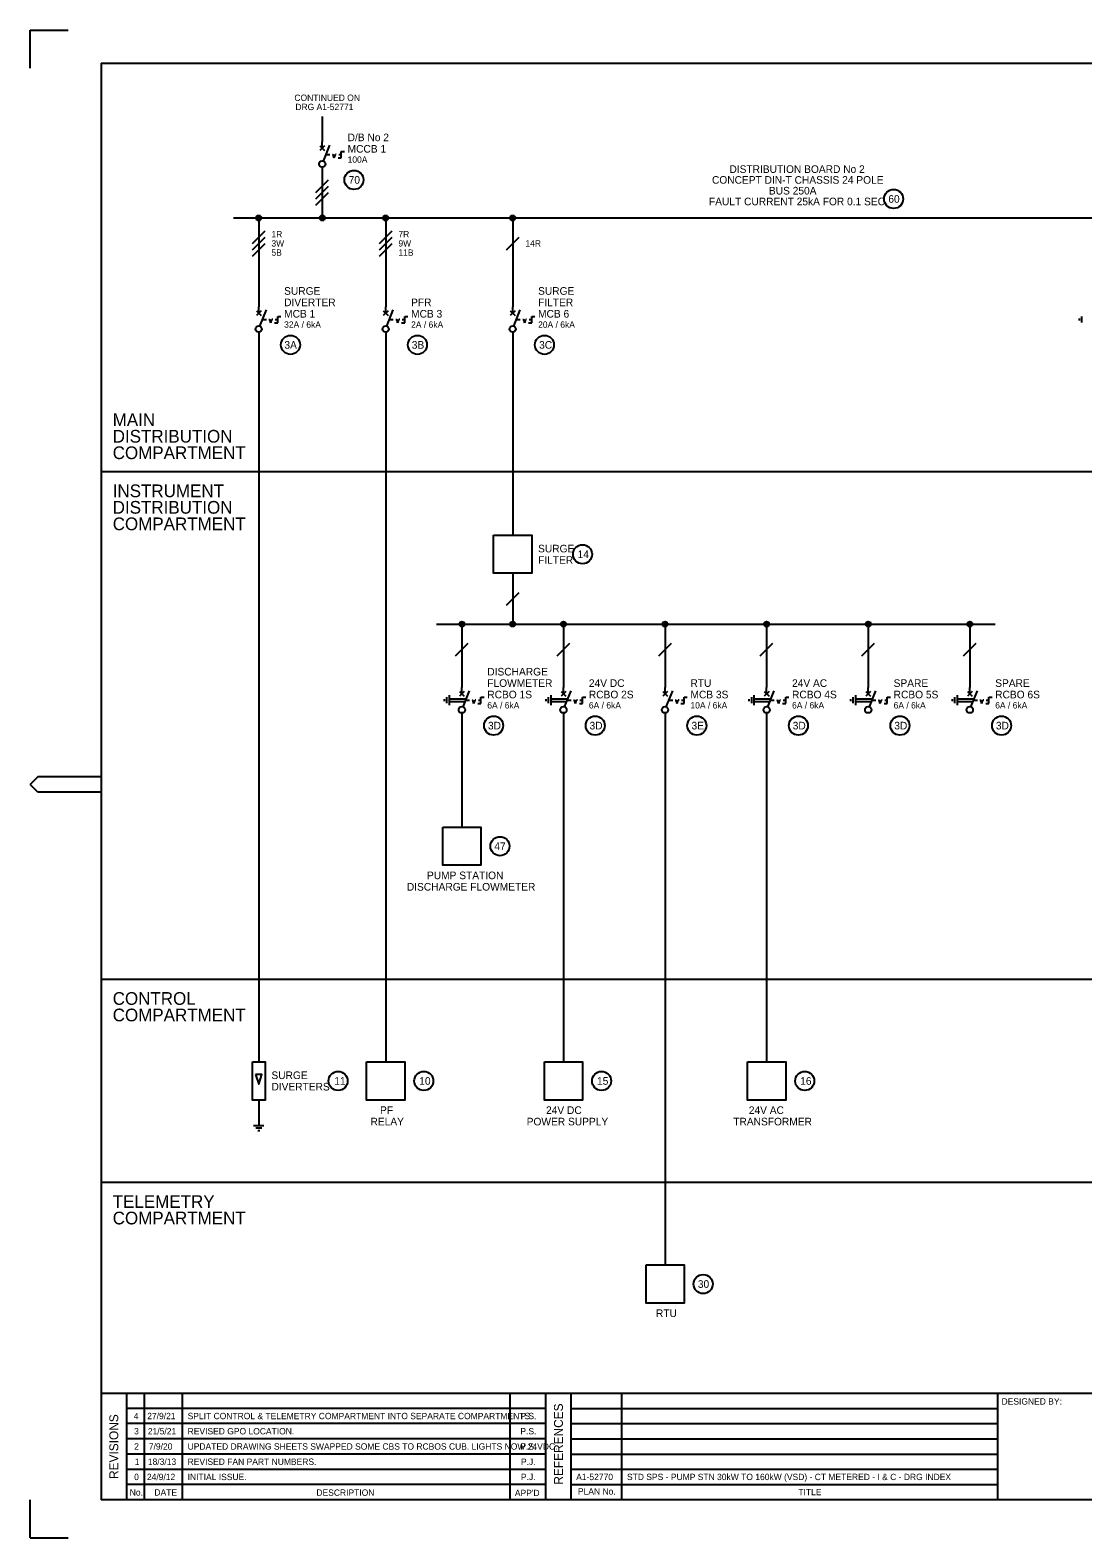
# Model space of a CAD drawing. Extents: x 0 to 841, y 0 to 594.
# Drawn here: x 0 to 414, y 0 to 594 of the extents above; entities that cross this region are included whole.
import ezdxf

# ---------------------------------------------------------------- set-up
doc = ezdxf.new("R2010")
doc.units = 0
for name, color, linetype in [('A1BORDER', 7, 'Continuous'), ('Level 1', 7, 'Continuous'), ('Level 10', 7, 'Continuous')]:
    doc.layers.add(name, color=color, linetype=linetype)

msp = doc.modelspace()

# ---------------------------------------------------------------- linework, layer by layer
at = {"layer": 'A1BORDER'}
for p, q in [((0, 594), (15, 594)), ((0, 579), (0, 594)), ((28, 581), (829, 581)), ((28, 581), (28, 15)), ((3, 299.76), (0, 296.76)), ((28, 299.76), (3, 299.76)), ((3, 293.76), (0, 296.76)), ((28, 293.76), (3, 293.76)), ((28, 57), (829, 57)), ((38, 15), (38, 57)), ((45, 15), (45, 57)), ((60, 15), (60, 57)), ((189, 15), (189, 57)), ((203, 15), (203, 57)), ((213, 15), (213, 57)), ((233, 15), (233, 57)), ((381, 15), (381, 57)), ((203, 51), (38, 51)), ((213, 51), (381, 51)), ((203, 45), (38, 45)), ((213, 45), (381, 45)), ((203, 39), (38, 39)), ((213, 39), (381, 39)), ((203, 33), (38, 33)), ((213, 33), (381, 33)), ((38, 27), (203, 27)), ((213, 27), (381, 27)), ((203, 21), (38, 21)), ((213, 21), (381, 21)), ((0, 0), (0, 15)), ((829, 15), (28, 15)), ((0, 0), (15, 0))]:
    msp.add_line(p, q, dxfattribs=at)
at = {"layer": 'Level 1'}
for p, q in [((115, 560), (115, 550)), ((114.06, 548.44), (115.94, 546.56)), ((115.94, 548.44), (114.06, 546.56)), ((115, 547.5), (115, 550)), ((115.46, 542.41), (118, 548.75)), ((112.5, 530), (117.5, 535)), ((115, 540), (115, 520)), ((112.5, 527.5), (117.5, 532.5)), ((112.5, 525), (117.5, 530)), ((80, 520), (740, 520)), ((90, 520), (90, 485)), ((140, 520), (140, 485)), ((190, 520), (190, 485)), ((87.5, 510), (92.5, 515)), ((87.5, 507.5), (92.5, 512.5)), ((137.5, 510), (142.5, 515)), ((137.5, 507.5), (142.5, 512.5)), ((187.5, 507.5), (192.5, 512.5)), ((87.5, 505), (92.5, 510)), ((137.5, 505), (142.5, 510)), ((89.06, 483.44), (90.94, 481.56)), ((90.94, 483.44), (89.06, 481.56)), ((90, 482.5), (90, 485)), ((90.46, 477.41), (93, 483.75)), ((139.06, 483.44), (140.94, 481.56)), ((140.94, 483.44), (139.06, 481.56)), ((140, 482.5), (140, 485)), ((140.46, 477.41), (143, 483.75)), ((189.06, 483.44), (190.94, 481.56)), ((190.94, 483.44), (189.06, 481.56)), ((190, 482.5), (190, 485)), ((190.46, 477.41), (193, 483.75)), ((90, 475), (90, 187.5)), ((140, 475), (140, 187.5)), ((190, 475), (190, 395)), ((829, 420), (28, 420)), ((190, 380), (190, 360)), ((187.5, 367.5), (192.5, 372.5)), ((160, 360), (380, 360)), ((170, 360), (170, 335)), ((210, 360), (210, 335)), ((250, 360), (250, 335)), ((290, 360), (290, 335)), ((330, 360), (330, 335)), ((370, 360), (370, 335)), ((167.5, 347.5), (172.5, 352.5)), ((207.5, 347.5), (212.5, 352.5)), ((247.5, 347.5), (252.5, 352.5)), ((287.5, 347.5), (292.5, 352.5)), ((327.5, 347.5), (332.5, 352.5)), ((367.5, 347.5), (372.5, 352.5)), ((169.06, 333.44), (170.94, 331.56)), ((170.94, 333.44), (169.06, 331.56)), ((170, 332.5), (170, 335)), ((170.46, 327.41), (173, 333.75)), ((209.06, 333.44), (210.94, 331.56)), ((210.94, 333.44), (209.06, 331.56)), ((210, 332.5), (210, 335)), ((210.46, 327.41), (213, 333.75)), ((249.06, 333.44), (250.94, 331.56)), ((250.94, 333.44), (249.06, 331.56)), ((250, 332.5), (250, 335)), ((250.46, 327.41), (253, 333.75)), ((289.06, 333.44), (290.94, 331.56)), ((290.94, 333.44), (289.06, 331.56)), ((290, 332.5), (290, 335)), ((290.46, 327.41), (293, 333.75)), ((329.06, 333.44), (330.94, 331.56)), ((330.94, 333.44), (329.06, 331.56)), ((330, 332.5), (330, 335)), ((330.46, 327.41), (333, 333.75)), ((369.06, 333.44), (370.94, 331.56)), ((370.94, 333.44), (369.06, 331.56)), ((370, 332.5), (370, 335)), ((370.46, 327.41), (373, 333.75)), ((165, 330.5), (171.7, 330.5)), ((165, 329.5), (171.3, 329.5)), ((205, 330.5), (211.7, 330.5)), ((205, 329.5), (211.3, 329.5)), ((285, 330.5), (291.7, 330.5)), ((285, 329.5), (291.3, 329.5)), ((325, 330.5), (331.7, 330.5)), ((325, 329.5), (331.3, 329.5)), ((365, 330.5), (371.7, 330.5)), ((365, 329.5), (371.3, 329.5)), ((170, 325), (170, 280)), ((210, 325), (210, 187.5)), ((250, 325), (250, 107.5)), ((290, 325), (290, 187.5)), ((829, 220), (28, 220)), ((90, 172.5), (90, 162.5)), ((480, 140), (28, 140))]:
    msp.add_line(p, q, dxfattribs=at)
for points in [[(182.5, 395), (197.5, 395), (197.5, 380), (182.5, 380)], [(162.5, 280), (177.5, 280), (177.5, 265), (162.5, 265)], [(87.5, 187.5), (92.5, 187.5), (92.5, 172.5), (87.5, 172.5)], [(132.5, 187.5), (147.5, 187.5), (147.5, 172.5), (132.5, 172.5)], [(202.5, 187.5), (217.5, 187.5), (217.5, 172.5), (202.5, 172.5)], [(282.5, 187.5), (297.5, 187.5), (297.5, 172.5), (282.5, 172.5)], [(88.75, 182.5), (90, 178.75), (91.25, 182.5)], [(242.5, 107.5), (257.5, 107.5), (257.5, 92.5), (242.5, 92.5)]]:
    msp.add_lwpolyline(points, close=True, dxfattribs=at)
for centre, radius in [((115, 541.25), 1.25), ((127.5, 535), 3.75), ((340, 527.5), 3.75), ((90, 476.25), 1.25), ((140, 476.25), 1.25), ((190, 476.25), 1.25), ((102.5, 470), 3.75), ((152.5, 470), 3.75), ((202.5, 470), 3.75), ((217.5, 387.5), 3.75), ((170, 326.25), 1.25), ((210, 326.25), 1.25), ((250, 326.25), 1.25), ((290, 326.25), 1.25), ((330, 326.25), 1.25), ((370, 326.25), 1.25), ((182.5, 320), 3.75), ((222.5, 320), 3.75), ((262.5, 320), 3.75), ((302.5, 320), 3.75), ((342.5, 320), 3.75), ((382.5, 320), 3.75), ((185, 272.5), 3.75), ((121.25, 180), 3.75), ((155, 180), 3.75), ((225, 180), 3.75), ((305, 180), 3.75), ((265, 100), 3.75)]:
    msp.add_circle(centre, radius, dxfattribs=at)
at = {"layer": 'Level 10'}
for p, q in [((116.5, 545), (118, 545)), ((119, 545), (119.33, 545)), ((119.75, 543.75), (119.33, 545)), ((119.75, 543.75), (120.17, 545)), ((120.5, 545), (120.17, 545)), ((121.25, 543.75), (122.5, 543.75)), ((121.5, 545), (122.5, 545)), ((122.5, 543.75), (122.5, 546.25)), ((122.5, 546.25), (123.75, 546.25)), ((89.01, 520.1), (90.99, 520.1)), ((89.02, 519.8), (90.98, 519.8)), ((89.08, 520.4), (90.92, 520.4)), ((89.13, 519.5), (90.87, 519.5)), ((89.29, 520.7), (90.71, 520.7)), ((89.4, 519.2), (90.6, 519.2)), ((90, 521), (90, 521)), ((114.01, 520.1), (115.99, 520.1)), ((114.02, 519.8), (115.98, 519.8)), ((114.08, 520.4), (115.92, 520.4)), ((114.13, 519.5), (115.87, 519.5)), ((114.29, 520.7), (115.71, 520.7)), ((114.4, 519.2), (115.6, 519.2)), ((115, 521), (115, 521)), ((139.01, 520.1), (140.99, 520.1)), ((139.02, 519.8), (140.98, 519.8)), ((139.08, 520.4), (140.92, 520.4)), ((139.13, 519.5), (140.87, 519.5)), ((139.29, 520.7), (140.71, 520.7)), ((139.4, 519.2), (140.6, 519.2)), ((140, 521), (140, 521)), ((189.01, 520.1), (190.99, 520.1)), ((189.02, 519.8), (190.98, 519.8)), ((189.08, 520.4), (190.92, 520.4)), ((189.13, 519.5), (190.87, 519.5)), ((189.29, 520.7), (190.71, 520.7)), ((189.4, 519.2), (190.6, 519.2)), ((190, 521), (190, 521)), ((97.5, 478.75), (97.5, 481.25)), ((97.5, 481.25), (98.75, 481.25)), ((147.5, 478.75), (147.5, 481.25)), ((147.5, 481.25), (148.75, 481.25)), ((197.5, 478.75), (197.5, 481.25)), ((197.5, 481.25), (198.75, 481.25)), ((414, 481.2), (414, 478.8)), ((91.5, 480), (93, 480)), ((94, 480), (94.33, 480)), ((94.75, 478.75), (94.33, 480)), ((94.75, 478.75), (95.17, 480)), ((95.5, 480), (95.17, 480)), ((96.25, 478.75), (97.5, 478.75)), ((96.5, 480), (97.5, 480)), ((141.5, 480), (143, 480)), ((144, 480), (144.33, 480)), ((144.75, 478.75), (144.33, 480)), ((144.75, 478.75), (145.17, 480)), ((145.5, 480), (145.17, 480)), ((146.25, 478.75), (147.5, 478.75)), ((146.5, 480), (147.5, 480)), ((191.5, 480), (193, 480)), ((194, 480), (194.33, 480)), ((194.75, 478.75), (194.33, 480)), ((194.75, 478.75), (195.17, 480)), ((195.5, 480), (195.17, 480)), ((196.25, 478.75), (197.5, 478.75)), ((196.5, 480), (197.5, 480)), ((413, 480.4), (413, 479.6)), ((169.01, 360.1), (170.99, 360.1)), ((169.02, 359.8), (170.98, 359.8)), ((169.08, 360.4), (170.92, 360.4)), ((169.13, 359.5), (170.87, 359.5)), ((169.29, 360.7), (170.71, 360.7)), ((169.4, 359.2), (170.6, 359.2)), ((170, 361), (170, 361)), ((189.01, 360.1), (190.99, 360.1)), ((189.02, 359.8), (190.98, 359.8)), ((189.08, 360.4), (190.92, 360.4)), ((189.13, 359.5), (190.87, 359.5)), ((189.29, 360.7), (190.71, 360.7)), ((189.4, 359.2), (190.6, 359.2)), ((190, 361), (190, 361)), ((209.01, 360.1), (210.99, 360.1)), ((209.02, 359.8), (210.98, 359.8)), ((209.08, 360.4), (210.92, 360.4)), ((209.13, 359.5), (210.87, 359.5)), ((209.29, 360.7), (210.71, 360.7)), ((209.4, 359.2), (210.6, 359.2)), ((210, 361), (210, 361)), ((249.01, 360.1), (250.99, 360.1)), ((249.02, 359.8), (250.98, 359.8)), ((249.08, 360.4), (250.92, 360.4)), ((249.13, 359.5), (250.87, 359.5)), ((249.29, 360.7), (250.71, 360.7)), ((249.4, 359.2), (250.6, 359.2)), ((250, 361), (250, 361)), ((289.01, 360.1), (290.99, 360.1)), ((289.02, 359.8), (290.98, 359.8)), ((289.08, 360.4), (290.92, 360.4)), ((289.13, 359.5), (290.87, 359.5)), ((289.29, 360.7), (290.71, 360.7)), ((289.4, 359.2), (290.6, 359.2)), ((290, 361), (290, 361)), ((329.01, 360.1), (330.99, 360.1)), ((329.02, 359.8), (330.98, 359.8)), ((329.08, 360.4), (330.92, 360.4)), ((329.13, 359.5), (330.87, 359.5)), ((329.29, 360.7), (330.71, 360.7)), ((329.4, 359.2), (330.6, 359.2)), ((330, 361), (330, 361)), ((369.01, 360.1), (370.99, 360.1)), ((369.02, 359.8), (370.98, 359.8)), ((369.08, 360.4), (370.92, 360.4)), ((369.13, 359.5), (370.87, 359.5)), ((369.29, 360.7), (370.71, 360.7)), ((369.4, 359.2), (370.6, 359.2)), ((370, 361), (370, 361)), ((163, 330.4), (163, 329.6)), ((164, 331.2), (164, 328.8)), ((165, 332), (165, 328)), ((171.5, 330), (173, 330)), ((174, 330), (174.33, 330)), ((174.75, 328.75), (174.33, 330)), ((174.75, 328.75), (175.17, 330)), ((175.5, 330), (175.17, 330)), ((176.25, 328.75), (177.5, 328.75)), ((176.5, 330), (177.5, 330)), ((177.5, 328.75), (177.5, 331.25)), ((177.5, 331.25), (178.75, 331.25)), ((203, 330.4), (203, 329.6)), ((204, 331.2), (204, 328.8)), ((205, 332), (205, 328)), ((211.5, 330), (213, 330)), ((214, 330), (214.33, 330)), ((214.75, 328.75), (214.33, 330)), ((214.75, 328.75), (215.17, 330)), ((215.5, 330), (215.17, 330)), ((216.25, 328.75), (217.5, 328.75)), ((216.5, 330), (217.5, 330)), ((217.5, 328.75), (217.5, 331.25)), ((217.5, 331.25), (218.75, 331.25)), ((251.5, 330), (253, 330)), ((254, 330), (254.33, 330)), ((254.75, 328.75), (254.33, 330)), ((254.75, 328.75), (255.17, 330)), ((255.5, 330), (255.17, 330)), ((256.25, 328.75), (257.5, 328.75)), ((256.5, 330), (257.5, 330)), ((257.5, 328.75), (257.5, 331.25)), ((257.5, 331.25), (258.75, 331.25)), ((283, 330.4), (283, 329.6)), ((284, 331.2), (284, 328.8)), ((285, 332), (285, 328)), ((291.5, 330), (293, 330)), ((294, 330), (294.33, 330)), ((294.75, 328.75), (294.33, 330)), ((294.75, 328.75), (295.17, 330)), ((295.5, 330), (295.17, 330)), ((296.25, 328.75), (297.5, 328.75)), ((296.5, 330), (297.5, 330)), ((297.5, 328.75), (297.5, 331.25)), ((297.5, 331.25), (298.75, 331.25)), ((323, 330.4), (323, 329.6)), ((324, 331.2), (324, 328.8)), ((325, 332), (325, 328)), ((331.5, 330), (333, 330)), ((334, 330), (334.33, 330)), ((334.75, 328.75), (334.33, 330)), ((334.75, 328.75), (335.17, 330)), ((335.5, 330), (335.17, 330)), ((336.25, 328.75), (337.5, 328.75)), ((336.5, 330), (337.5, 330)), ((337.5, 328.75), (337.5, 331.25)), ((337.5, 331.25), (338.75, 331.25)), ((363, 330.4), (363, 329.6)), ((364, 331.2), (364, 328.8)), ((365, 332), (365, 328)), ((371.5, 330), (373, 330)), ((374, 330), (374.33, 330)), ((374.75, 328.75), (374.33, 330)), ((374.75, 328.75), (375.17, 330)), ((375.5, 330), (375.17, 330)), ((376.25, 328.75), (377.5, 328.75)), ((376.5, 330), (377.5, 330)), ((377.5, 328.75), (377.5, 331.25)), ((377.5, 331.25), (378.75, 331.25)), ((88, 162.5), (92, 162.5)), ((88.8, 161.5), (91.2, 161.5)), ((89.6, 160.5), (90.4, 160.5))]:
    msp.add_line(p, q, dxfattribs=at)
for centre in [(90, 520), (115, 520), (140, 520), (190, 520), (170, 360), (190, 360), (210, 360), (250, 360), (290, 360), (330, 360), (370, 360)]:
    msp.add_circle(centre, 1, dxfattribs=at)

# ---------------------------------------------------------------- texts
at = {"layer": 'A1BORDER'}
for s, p in [('DESIGNED BY:', (382.5, 52.5)), ('No.', (39.21, 16.65)), ('DATE', (48.92, 16.65)), ('DESCRIPTION', (112.71, 16.57)), ("APP'D", (190.85, 16.44)), ('PLAN No.', (215.69, 17.06)), ('TITLE', (302.5, 16.81))]:
    msp.add_text(s, height=2.5, dxfattribs=at).set_placement(p)
for s, p in [('REVISIONS', (34.68, 23.2)), ('REFERENCES', (209.76, 20.96))]:
    msp.add_text(s, height=3.5, rotation=90, dxfattribs=at).set_placement(p)
at = {"layer": 'Level 1'}
for s, height, p in [('CONTINUED ON', 2.5, (104.04, 566.12)), ('DRG A1-52771', 2.5, (104.42, 562.5)), ('D/B No 2', 3, (125, 550.25)), ('MCCB 1', 3, (125, 545.75)), ('100A', 2.5, (125, 541.75)), ('DISTRIBUTION BOARD No 2', 3, (275.35, 537.75)), ('70', 3, (125.41, 533.5)), ('CONCEPT DIN-T CHASSIS 24 POLE', 3, (268.47, 533.5)), ('BUS 250A', 3, (290.89, 529.25)), ('60', 3, (337.91, 526)), ('FAULT CURRENT 25kA FOR 0.1 SEC', 3, (267.28, 525)), ('3W', 2.5, (95, 508.75)), ('1R', 2.5, (95, 512.37)), ('9W', 2.5, (145, 508.75)), ('7R', 2.5, (145, 512.37)), ('14R', 2.5, (195, 508.75)), ('5B', 2.5, (95, 505.13)), ('11B', 2.5, (145, 505.13)), ('SURGE', 3, (100, 489.75)), ('DIVERTER', 3, (100, 485.25)), ('PFR', 3, (150, 485.25)), ('SURGE', 3, (200, 489.75)), ('FILTER', 3, (200, 485.25)), ('MCB 1', 3, (100, 480.75)), ('MCB 3', 3, (150, 480.75)), ('MCB 6', 3, (200, 480.75)), ('32A / 6kA', 2.5, (100, 476.75)), ('2A / 6kA', 2.5, (150, 476.75)), ('20A / 6kA', 2.5, (200, 476.75)), ('3A', 3, (100.11, 468.5)), ('3B', 3, (150.26, 468.5)), ('3C', 3, (200.41, 468.5)), ('MAIN', 5, (32.5, 438)), ('DISTRIBUTION', 5, (32.5, 431.5)), ('COMPARTMENT', 5, (32.5, 425)), ('INSTRUMENT', 5, (32.5, 410)), ('DISTRIBUTION', 5, (32.5, 403.5)), ('COMPARTMENT', 5, (32.5, 397)), ('SURGE', 3, (200, 388.25)), ('FILTER', 3, (200, 383.75)), ('14', 3, (215.56, 386)), ('DISCHARGE', 3, (180, 339.75)), ('FLOWMETER', 3, (180, 335.25)), ('RCBO 1S', 3, (180, 330.75)), ('24V DC', 3, (220, 335.25)), ('RCBO 2S', 3, (220, 330.75)), ('RTU', 3, (260, 335.25)), ('MCB 3S', 3, (260, 330.75)), ('24V AC', 3, (300, 335.25)), ('RCBO 4S', 3, (300, 330.75)), ('SPARE', 3, (340, 335.25)), ('RCBO 5S', 3, (340, 330.75)), ('SPARE', 3, (380, 335.25)), ('RCBO 6S', 3, (380, 330.75)), ('6A / 6kA', 2.5, (180, 326.75)), ('6A / 6kA', 2.5, (220, 326.75)), ('10A / 6kA', 2.5, (260, 326.75)), ('6A / 6kA', 2.5, (300, 326.75)), ('6A / 6kA', 2.5, (340, 326.75)), ('6A / 6kA', 2.5, (380, 326.75)), ('3D', 3, (180.26, 318.5)), ('3D', 3, (220.26, 318.5)), ('3E', 3, (260.41, 318.5)), ('3D', 3, (300.26, 318.5)), ('3D', 3, (340.26, 318.5)), ('3D', 3, (380.26, 318.5)), ('47', 3, (182.76, 271)), ('PUMP STATION', 3, (156.25, 259.5)), ('DISCHARGE FLOWMETER', 3, (148.33, 255)), ('CONTROL', 5, (32.5, 210)), ('COMPARTMENT', 5, (32.5, 203.5)), ('SURGE', 3, (95, 180.75)), ('DIVERTERS', 3, (95, 176.25)), ('11', 3, (119.76, 178.5)), ('10', 3, (153.21, 178.5)), ('15', 3, (223.21, 178.5)), ('16', 3, (303.21, 178.5)), ('PF', 3, (137.76, 167)), ('24V DC', 3, (203.13, 167)), ('24V AC', 3, (282.98, 167)), ('RELAY', 3, (134.02, 162.5)), ('POWER SUPPLY', 3, (195.51, 162.5)), ('TRANSFORMER', 3, (276.85, 162.5)), ('TELEMETRY', 5, (32.5, 130)), ('COMPARTMENT', 5, (32.5, 123.5)), ('30', 3, (262.91, 98.5)), ('RTU', 3, (246.41, 87)), ('4', 2.5, (40.82, 46.75)), ('27/9/21', 2.5, (46.09, 46.75)), ('SPLIT CONTROL & TELEMETRY COMPARTMENT INTO SEPARATE COMPARTMENTS.', 2.5, (62, 46.75)), ('P.S.', 2.5, (193.02, 46.75)), ('3', 2.5, (40.94, 40.75)), ('21/5/21', 2.5, (46.34, 40.75)), ('REVISED GPO LOCATION.', 2.5, (62, 40.75)), ('P.S.', 2.5, (193.02, 40.75)), ('2', 2.5, (40.94, 34.75)), ('7/9/20', 2.5, (46.72, 34.75)), ('UPDATED DRAWING SHEETS SWAPPED SOME CBS TO RCBOS CUB. LIGHTS NOW 24VDC.', 2.5, (62, 34.75)), ('P.S.', 2.5, (193.02, 34.75)), ('1', 2.5, (41.19, 28.75)), ('18/3/13', 2.5, (46.34, 28.75)), ('REVISED FAN PART NUMBERS.', 2.5, (62, 28.75)), ('P.J.', 2.5, (193.26, 28.75)), ('0', 2.5, (40.94, 22.75)), ('24/9/12', 2.5, (45.97, 22.75)), ('INITIAL ISSUE.', 2.5, (62, 22.75)), ('P.J.', 2.5, (193.26, 22.75)), ('A1-52770', 2.5, (215, 22.75)), ('STD SPS - PUMP STN 30kW TO 160kW (VSD) - CT METERED - I & C - DRG INDEX', 2.5, (235, 22.75))]:
    msp.add_text(s, height=height, dxfattribs=at).set_placement(p)

doc.saveas('drawing.dxf')
